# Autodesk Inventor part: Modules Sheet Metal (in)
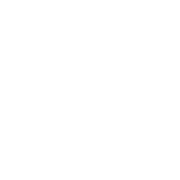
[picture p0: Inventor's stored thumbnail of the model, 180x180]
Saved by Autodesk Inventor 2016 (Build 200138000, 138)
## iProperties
Created: 2014-08
Part Number: Modules Sheet Metal (in)
Material: Generic
Document SubType Name: Sheet Metal
Designer: Wally
Density: 1 g/cm^3
Sheet Metal Rule: Default
Appearance: Default
Author: Wally
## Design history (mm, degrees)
node "Sketch1"
other parameters: "Thickness" = 3.048, "BendRadius" = 3.048 (= Thickness), "BendReliefWidth" = 3.048 (= Thickness), "BendReliefDepth" = 1.524 (= 0.5 x Thickness), "CornerReliefSize" = 12.192 (= 4 x Thickness), "SeamGap" = 0.01, "MinimumRemnant" = 6.096 (= 2 x Thickness), "TransitionRadius" = 3.048 (= BendRadius), "JacobiRadiusSize" = 3.048 (= Thickness), "GapSize" = 3.048 (= Thickness)
